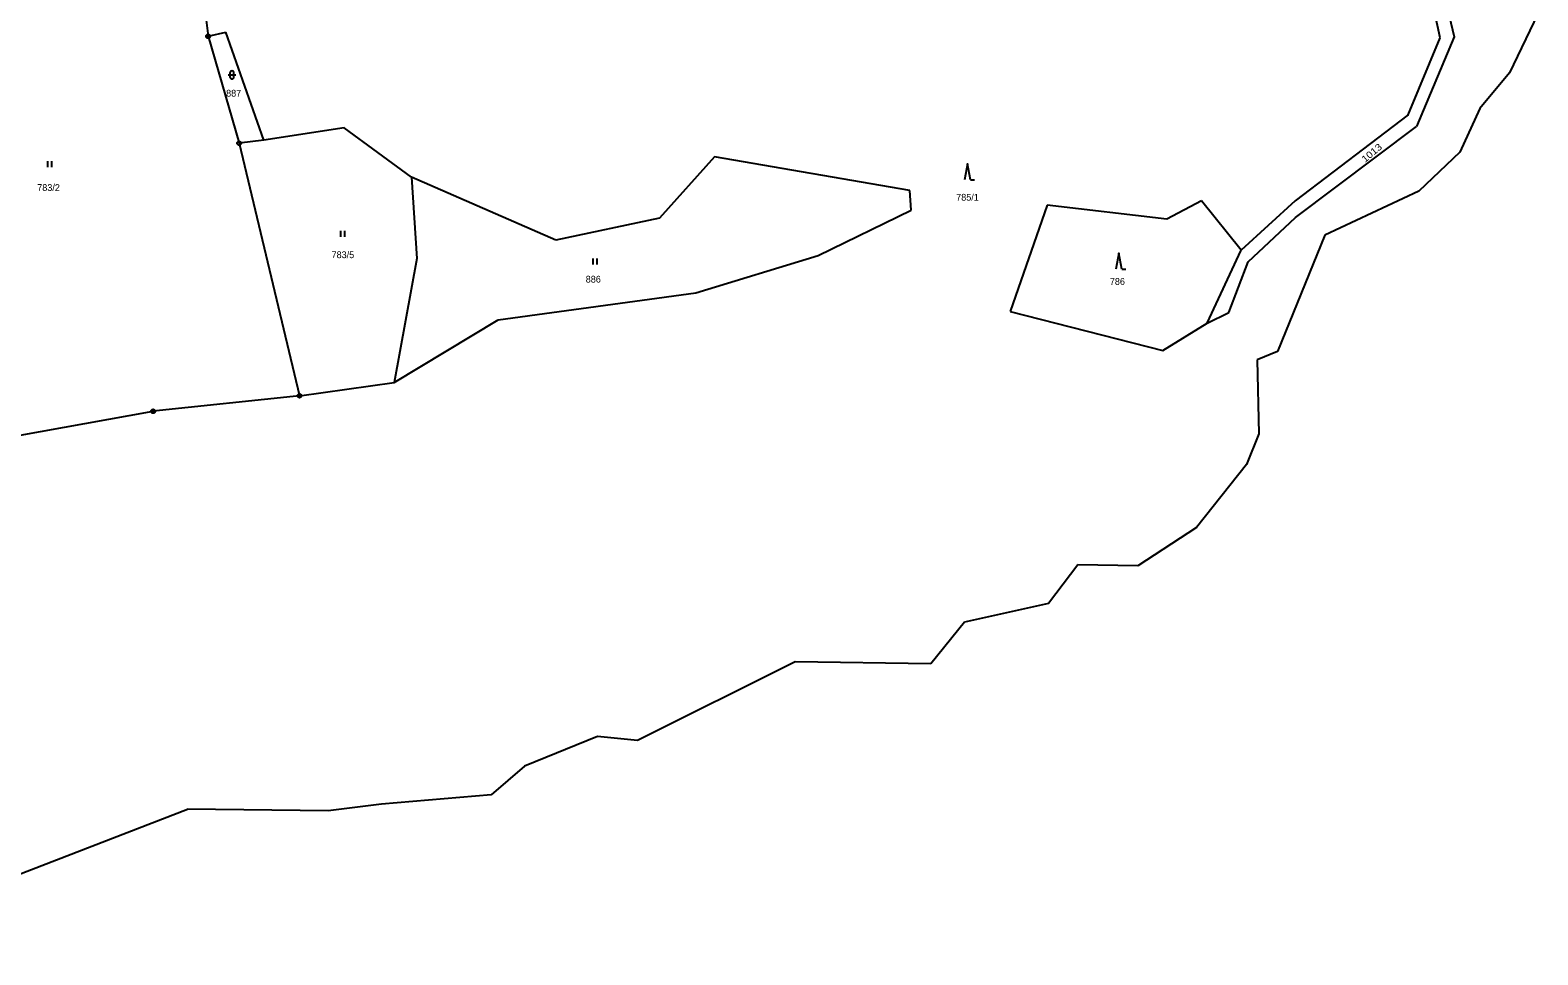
# Model space of a CAD drawing. Extents: x -754970 to -752637, y -970569 to -968179.
# Drawn here: x -753799.4 to -753421, y -970350 to -970118 of the extents above; entities that cross this region are included whole.
import ezdxf
from ezdxf.enums import TextEntityAlignment as Align

# ---------------------------------------------------------------- set-up
doc = ezdxf.new("R2010")
doc.units = 0
doc.header["$LTSCALE"] = 0.68
for name, color, linetype, lineweight in [('1', 7, 'Continuous', 25), ('3', 7, 'Continuous', 25), ('8', 7, 'Continuous', 25)]:
    doc.layers.add(name, color=color, linetype=linetype, lineweight=lineweight)
doc.layers.add('2', color=7, linetype='Continuous')

msp = doc.modelspace()

# ---------------------------------------------------------------- linework, layer by layer
at = {"layer": '1'}
for p, q in [((-753761.6, -970063.86), (-753754.71, -970119.59)), ((-753445.5, -970119.97), (-753449.37, -970102.27)), ((-753446.1, -970102.36), (-753442.04, -970119.68)), ((-753421.02, -970113.93), (-753428.14, -970128.76)), ((-753754.71, -970119.59), (-753750.26, -970118.52)), ((-753754.71, -970119.59), (-753746.91, -970146.4)), ((-753740.74, -970145.6), (-753750.26, -970118.52)), ((-753453.58, -970139.3), (-753445.5, -970119.97)), ((-753442.04, -970119.68), (-753451.47, -970142.18)), ((-753428.14, -970128.76), (-753435.59, -970137.67)), ((-753453.58, -970139.3), (-753481.94, -970160.84)), ((-753435.59, -970137.67), (-753440.56, -970148.63)), ((-753720.58, -970142.54), (-753740.74, -970145.6)), ((-753703.7, -970154.89), (-753720.58, -970142.54)), ((-753481.86, -970165.02), (-753451.47, -970142.18)), ((-753740.74, -970145.6), (-753746.91, -970146.4)), ((-753746.91, -970146.4), (-753731.78, -970209.77)), ((-753627.63, -970149.83), (-753641.4, -970165.2)), ((-753578.64, -970158.29), (-753627.63, -970149.83)), ((-753440.56, -970148.63), (-753450.91, -970158.47)), ((-753703.7, -970154.89), (-753702.34, -970175.29)), ((-753667.45, -970170.76), (-753703.7, -970154.89)), ((-753578.3, -970163.16), (-753578.64, -970158.29)), ((-753450.91, -970158.47), (-753474.47, -970169.47)), ((-753544.18, -970161.91), (-753553.46, -970188.62)), ((-753514.11, -970165.47), (-753544.18, -970161.91)), ((-753505.4, -970160.88), (-753514.11, -970165.47)), ((-753495.47, -970173.25), (-753505.4, -970160.88)), ((-753481.94, -970160.84), (-753495.47, -970173.25)), ((-753641.4, -970165.2), (-753667.45, -970170.76)), ((-753601.64, -970174.6), (-753578.3, -970163.16)), ((-753493.69, -970176.15), (-753481.86, -970165.02)), ((-753474.47, -970169.47), (-753486.31, -970198.68)), ((-753503.99, -970191.52), (-753495.47, -970173.25)), ((-753702.34, -970175.29), (-753708, -970206.45)), ((-753632.33, -970183.9), (-753601.64, -970174.6)), ((-753498.56, -970188.9), (-753493.69, -970176.15)), ((-753681.95, -970190.7), (-753632.33, -970183.9)), ((-753553.46, -970188.62), (-753515.14, -970198.36)), ((-753503.99, -970191.52), (-753498.56, -970188.9)), ((-753708, -970206.45), (-753681.95, -970190.7)), ((-753515.14, -970198.36), (-753503.99, -970191.52)), ((-753486.31, -970198.68), (-753491.43, -970200.76)), ((-753491.43, -970200.76), (-753491.07, -970219.34)), ((-753731.78, -970209.77), (-753708, -970206.45)), ((-753731.78, -970209.77), (-753768.51, -970213.65)), ((-753817.67, -970222.43), (-753768.51, -970213.65)), ((-753491.07, -970219.34), (-753494.15, -970227)), ((-753494.15, -970227), (-753506.68, -970242.77)), ((-753506.68, -970242.77), (-753521.38, -970252.43)), ((-753536.42, -970252.18), (-753543.84, -970261.85)), ((-753521.38, -970252.43), (-753536.42, -970252.18)), ((-753543.84, -970261.85), (-753564.91, -970266.54)), ((-753564.91, -970266.54), (-753573.38, -970276.97)), ((-753607.37, -970276.5), (-753646.93, -970296.26)), ((-753573.38, -970276.97), (-753607.37, -970276.5)), ((-753656.96, -970295.23), (-753675.34, -970302.67)), ((-753646.93, -970296.26), (-753656.96, -970295.23)), ((-753675.34, -970302.67), (-753683.67, -970309.84)), ((-753683.67, -970309.84), (-753711.21, -970312.24)), ((-753854.66, -970350), (-753759.91, -970313.48)), ((-753724.54, -970313.91), (-753759.91, -970313.48)), ((-753711.21, -970312.24), (-753724.54, -970313.91))]:
    msp.add_line(p, q, dxfattribs=at)
at = {"layer": '3'}
for p, q in [((-753749.211, -970128.771), (-753749.211, -970129.772)), ((-753748.209, -970129.772), (-753748.209, -970128.771)), ((-753749.711, -970129.271), (-753747.709, -970129.271)), ((-753794.881, -970152.39), (-753794.881, -970150.89)), ((-753793.88, -970152.39), (-753793.88, -970150.89)), ((-753563.39, -970155.55), (-753562.394, -970155.55)), ((-753721.401, -970169.85), (-753721.401, -970168.35)), ((-753720.4, -970169.85), (-753720.4, -970168.35)), ((-753658.051, -970176.8), (-753658.051, -970175.3)), ((-753657.05, -970176.8), (-753657.05, -970175.3)), ((-753525.41, -970177.98), (-753524.414, -970177.98))]:
    msp.add_line(p, q, dxfattribs=at)
for points in [[(-753563.39, -970155.55), (-753564.14, -970151.55), (-753564.89, -970155.55)], [(-753525.41, -970177.98), (-753526.16, -970173.98), (-753526.91, -970177.98)]]:
    msp.add_lwpolyline(points, dxfattribs=at)
for centre, start, end in [((-753748.71, -970128.7709), 0, 180), ((-753748.71, -970129.7709), 180, 359.98789)]:
    msp.add_arc(centre, 0.5, start, end, dxfattribs=at)
at = {"layer": '8'}
for centre, radius in [((-753754.71, -970119.5899), 0.5), ((-753754.71, -970119.5899), 0.0303), ((-753746.91, -970146.3999), 0.5), ((-753746.91, -970146.3999), 0.0303), ((-753731.78, -970209.7699), 0.5), ((-753731.78, -970209.7699), 0.0303), ((-753768.51, -970213.6499), 0.5), ((-753768.51, -970213.6499), 0.0303)]:
    msp.add_circle(centre, radius, dxfattribs=at)

# ---------------------------------------------------------------- texts
at = {"layer": '2'}
for s, p in [('887', (-753748.289, -970134.715)), ('783/2', (-753794.74, -970158.375)), ('785/1', (-753564.14, -970160.815)), ('783/5', (-753720.88, -970175.235)), ('886', (-753658.049, -970181.365)), ('786', (-753526.529, -970181.935))]:
    msp.add_text(s, height=1.7, dxfattribs=at).set_placement(p, align=Align.CENTER)
at = {"layer": '2', "width": 1.15}
msp.add_text('1013', height=1.7, rotation=40, dxfattribs=at).set_placement((-753462.1584, -970149.4819), align=Align.CENTER)

doc.saveas('drawing.dxf')
